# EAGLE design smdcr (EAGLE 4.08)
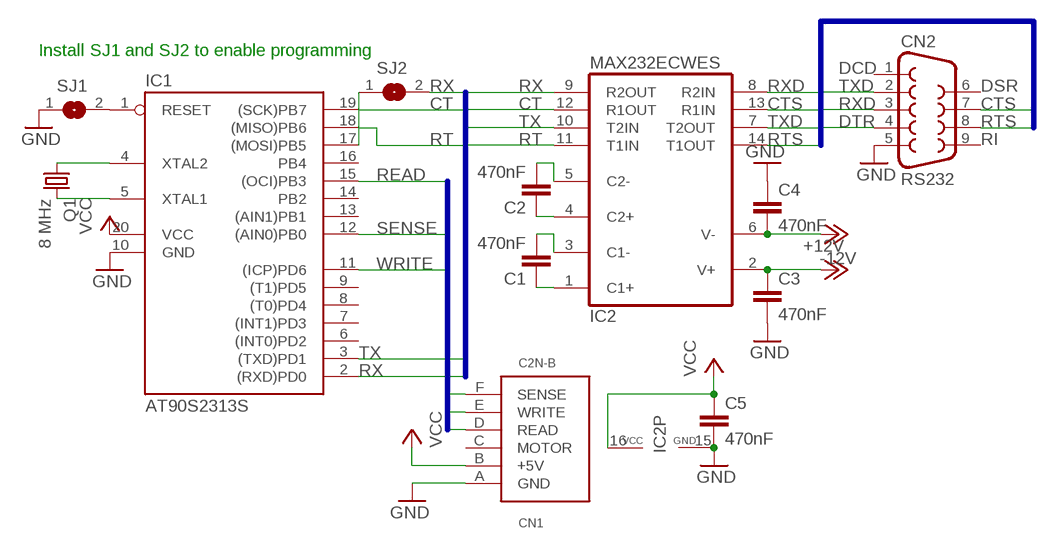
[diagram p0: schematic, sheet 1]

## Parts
C1  470nF  C-EUC0805  [C0805]
C2  470nF  C-EUC0805  [C0805]
C3  470nF  C-EUC0805  [C0805]
C4  470nF  C-EUC0805  [C0805]
C5  470nF  C-EUC0805  [C0805]
CN1  C2N-B  [C2N-B]
CN2  RS232  F09D  [F09D]
IC1  AT90S2313S  [SO-20L]
IC2  MAX232ECWES  [SO16]
Q1  8 MHz  SM49  [SM49]
SJ1  SJ  [SJ]
SJ2  SJW  [SJW]

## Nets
+12V: C3.2 IC2.2(V+)
-12V: C4.1 IC2.6(V-)
C1+: C1.2 IC2.1(C1+)
C1-: C1.1 IC2.3(C1-)
C2+: C2.2 IC2.4(C2+)
C2-: C2.1 IC2.5(C2-)
CT: IC1.19((SCK)PB7) IC2.12(R1OUT)
CTS: CN2.7 IC2.13(R1IN)
DTR: CN2.4
GND: C3.1 C4.2 C5.1 CN1.A(GND) CN2.5 IC1.10(GND) IC2.15(GND) SJ1.1
MOSI: IC1.17((MOSI)PB5) SJ2.1
READ: CN1.D(READ) IC1.15((OCI)PB3)
RESET: IC1.1(RESET) SJ1.2
RT: IC1.18((MISO)PB6) IC2.11(T1IN)
RTS: CN2.8 IC2.14(T1OUT)
RX: IC1.2((RXD)PD0) IC2.9(R2OUT) SJ2.2
RXD: CN2.3 IC2.8(R2IN)
SENSE: CN1.F(SENSE) IC1.12((AIN0)PB0)
TX: IC1.3((TXD)PD1) IC2.10(T2IN)
TXD: CN2.2 IC2.7(T2OUT)
VCC: C5.2 CN1.B(+5V) IC1.20(VCC) IC2.16(VCC)
WRITE: CN1.E(WRITE) IC1.11((ICP)PD6)
XTAL1: IC1.5(XTAL1) Q1.2
XTAL2: IC1.4(XTAL2) Q1.1
Unconnected: CN1.C(MOTOR) CN2.1 CN2.6 CN2.9 IC1.6((INT0)PD2) IC1.7((INT1)PD3) IC1.8((T0)PD4) IC1.9((T1)PD5) IC1.13((AIN1)PB1) IC1.14(PB2) IC1.16(PB4)

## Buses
WRITE,READ,SENSE,MOTOR
DTR,CTS,RTS,RXD,TXD,DSR,RI,DCD
RX,TX,CT,RT

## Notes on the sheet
- Install SJ1 and SJ2 to enable programming
- DCD
- DSR
- RI

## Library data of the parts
C1-C5 = rcl:C-EU: CAPACITOR, European symbol
CN1 = vic-20:C2N: Datassette connector
CN2 = con-subd:F09D: HARTING SUB-D
IC1 = atmel:AT90S2313: MICROCONTROLLER 2 Kbytes FLASH 128 bytes SRAM 128 bytes EEPROM UART
IC2 = maxim:MAX232ECWE: RS232 TRANSCEIVER
Q1 = crystal:SM49: CRYSTAL
SJ1 SJ2 = jumper:SJ: SMD solder JUMPER

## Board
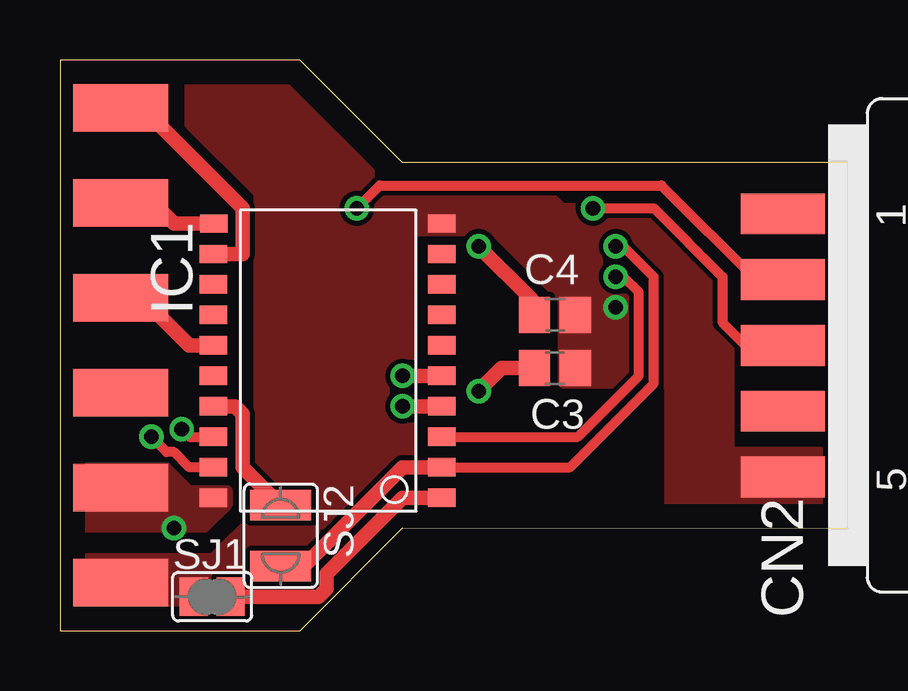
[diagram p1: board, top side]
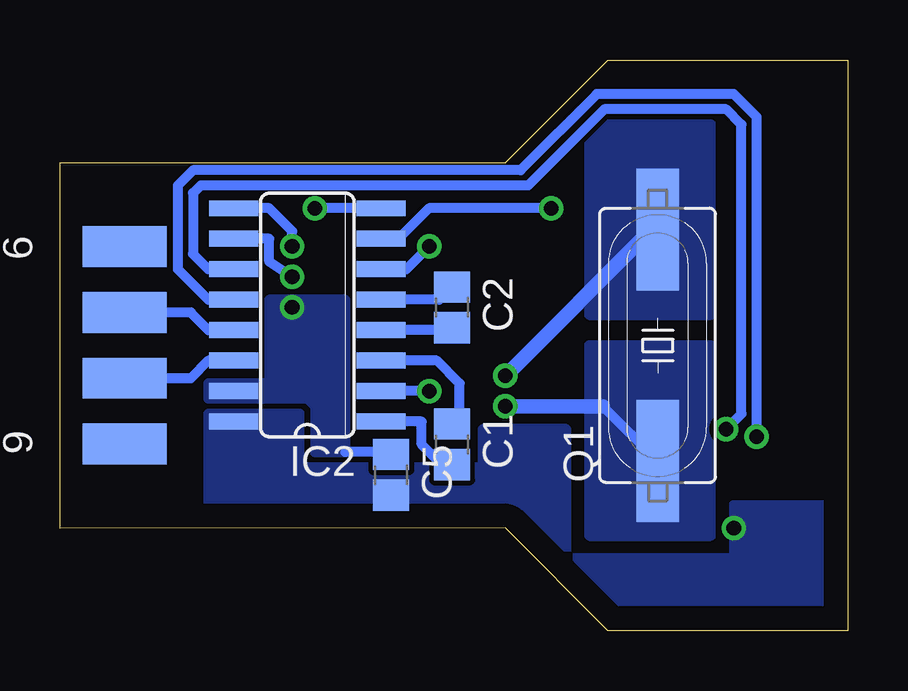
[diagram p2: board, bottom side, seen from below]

Size 32.85 x 23.8 mm. Coordinates in mm from the lower left corner, seen from the top.
Outline: 0,23.8 0,0 10,0 14.28,4.28 32.85,4.28 32.85,19.53 31.75,19.53 31.75,19.52 14.28,19.52 10,23.8 0,23.8
Copper layers used: Top, Bottom

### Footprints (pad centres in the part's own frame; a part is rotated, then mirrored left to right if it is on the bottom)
C0805 = smd 1.3 x 1.5: 1 -0.85,0; 2 0.85,0
C2N-B = smd 1.98 x 3.96 bottom: A -9.9,0; B -5.94,0; C -1.98,0; D 1.98,0; E 5.94,0; F 9.9,0
F09D = smd 1.7 x 3.5: 1 -5.486,-6.045; 2 -2.743,-6.045; 3 0,-6.045; 4 2.743,-6.045; 5 5.486,-6.045 | smd 1.7 x 3.5 bottom: 6 -4.115,-6.045; 7 -1.372,-6.045; 8 1.372,-6.045; 9 4.115,-6.045
SO-20L = smd 0.762 x 1.143: 1 -5.08,-5.131; 2 -3.81,-5.131; 3 -2.54,-5.131; 4 -1.27,-5.131; 5 0,-5.131; 6 1.27,-5.131; 7 2.54,-5.131; 8 3.81,-5.131; 9 5.08,-5.131; 10 6.35,-5.131; 11 6.35,4.369; 12 5.08,4.394; 13 3.81,4.394; 14 2.54,4.394; 15 1.27,4.394; 16 0,4.394; 17 -1.27,4.394; 18 -2.54,4.394; 19 -3.81,4.394; 20 -5.08,4.394
SO16 = smd 0.66 x 2.032: 1 -4.445,-3.073; 2 -3.175,-3.073; 3 -1.905,-3.073; 4 -0.635,-3.073; 5 0.635,-3.073; 6 1.905,-3.073; 7 3.175,-3.073; 8 4.445,-3.073; 9 4.445,3.073; 10 3.175,3.073; 11 1.905,3.073; 12 0.635,3.073; 13 -0.635,3.073; 14 -1.905,3.073; 15 -3.175,3.073; 16 -4.445,3.073
SM49 = smd 5.08 x 1.778: 1 -4.826,0; 2 4.826,0
SJ = smd 1.168 x 1.6: 1 -0.762,0; 2 0.762,0
SJW = smd 1.27 x 2.54: 1 -1.27,0; 2 1.27,0

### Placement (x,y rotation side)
C1  16.51,7.77 270 bottom
C2  16.51,13.49 270 bottom
C3  20.63,10.95 180 top
C4  20.63,13.17 0 top
C5  19.05,6.5 270 bottom
CN1  2.54,11.9 90 bottom
CN2  36.19,11.9 270 top
IC1  10.79,10.63 90 top
IC2  22.54,13.17 90 bottom
Q1  7.93,11.9 90 bottom
SJ1  6.34,1.42 0 top
SJ2  9.2,3.96 270 top

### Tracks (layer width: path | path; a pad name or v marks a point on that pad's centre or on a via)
+12V  (via drill 0.61 pad 0.61)
  Top 0.61: v17.46,10 18.41,10.95 C3.2
  Bottom 0.406: v17.46,10 IC2.2
-12V  (via drill 0.61)
  Top 0.406: C4.1 19.68,13.17
  Top 0.61: v17.46,16.03 19.68,13.81 19.68,13.17
  Bottom 0.406: IC2.6 18.41,15.08 v17.46,16.03
C1+
  Bottom 0.406: C1.2 16.93,6.92 17.78,7.77 17.78,8.73 IC2.1
C1-
  Bottom 0.406: IC2.3 17.14,11.27 16.19,10.31 16.19,8.62 C1.1
C2+
  Bottom 0.406: C2.2 16.4,12.54 IC2.4
C2-
  Bottom 0.406: C2.1 17.04,13.81 IC2.5
CT  (via drill 0.61)
  Top 0.406: v3.81,8.09 4.44,7.46 4.76,7.46 5.39,6.82 IC1.19
  Bottom 0.406: IC2.12 26.67,13.81 27.94,15.08 27.94,18.57 27.3,19.2 13.65,19.2 10.47,22.38 4.76,22.38 3.81,21.43 v3.81,8.09
CTS
  Bottom 0.406: IC2.13 26.67,12.54 27.4,13.27 CN2.7
GND  (via drill 0.61)
  Bottom 0.406: C5.1 19.15,7.46 20.95,7.46
  other vias: 23.17,13.49
  pour Top (no thermals): 20.95,10.31 25.39,10.31 25.39,4.28 31.75,4.28 31.75,7.46 27.94,7.46 27.94,13.81 24.12,17.62 20.95,17.62
  pour Top (no thermals): 20.95,17.62 20,18.57 14.6,18.57 9.84,23.33 5.71,23.33 5.39,23.01 5.39,21.11 8.25,18.25 8.25,4.92 6.34,3.01 -0.01,3.01 -0.01,0.47 14.6,0.47 14.6,16.66 18.09,16.66 20.95,13.81
  pour Bottom (no thermals): 24.12,10.31 26.67,10.31 26.67,9.68 22.54,9.68 22.22,9.36 22.22,7.46 20.95,7.46 20.95,13.81 24.12,13.81
MOSI
  Top 0.61: IC1.17 7.3,9.36 7.62,9.04 7.62,6.82 SJ2.1
READ
  Top 0.61: CN1.D 3.41,13.88 5.39,11.9 IC1.15
RESET
  Top 0.61: IC1.1 14.28,5.55 11.11,2.38 11.11,1.74 10.79,1.42 SJ1.2
RT  (via drill 0.61)
  Top 0.406: v5.08,8.41 5.39,8.09 IC1.18
  Bottom 0.406: IC2.11 26.67,15.08 27.3,15.71 27.3,18.25 26.98,18.57 13.33,18.57 10.15,21.74 5.08,21.74 4.44,21.11 4.44,9.04 v5.08,8.41
RTS
  Bottom 0.406: CN2.8 27.4,10.53 26.67,11.27 IC2.14
RX  (via drill 0.61 pad 0.61)
  Top 0.406: IC1.2 21.27,6.82 24.76,10.31 24.76,14.76 23.49,16.03 v23.17,16.03
  Top 0.61: IC1.2 14.28,6.82 10.15,2.69 SJ2.2
  Bottom 0.406: v23.17,16.03 23.17,16.66 24.12,17.62 IC2.9 26.03,17.62
RXD  (via drill 0.61 pad 0.61)
  Top 0.406: v22.22,17.62 24.76,17.62 27.62,14.76 27.62,12.85 28.57,11.9 CN2.3
  Bottom 0.406: IC2.8 v22.22,17.62
SENSE
  Top 0.406: 3.49,21.74 CN1.F
  Top 0.61: IC1.12 7.62,15.71 7.62,17.62 3.49,21.74
TX  (via drill 0.61 pad 0.61)
  Top 0.406: IC1.3 21.59,8.09 24.12,10.63 24.12,14.12 23.49,14.76 v23.17,14.76
  Bottom 0.406: v23.17,14.76 24.12,15.39 24.12,16.35 IC2.10
TXD  (via drill 0.61 pad 0.61)
  Top 0.406: v12.38,17.62 13.33,18.57 25.08,18.57 29,14.64 CN2.2
  Bottom 0.406: IC2.7 18.73,16.35 17.46,17.62 v12.38,17.62
VCC  (via drill 0.61)
  Bottom 0.406: IC2.16 26.03,8.73
  other vias: 4.76,4.28
  pour Top (no thermals): 6.03,4.28 0.63,4.28 0.63,6.82 4.44,6.82 5.39,5.87 6.98,5.87 6.98,5.23
  pour Bottom (no thermals): 22.86,9.04 26.67,9.04 26.67,0.15 0.31,0.15 0.31,5.23 4.76,5.23 4.76,3.01 11.74,3.01 11.74,8.41 15.23,8.41 15.23,6.82 22.86,6.82
WRITE
  Top 0.61: CN1.E 3.9,17.84 4.76,16.98 IC1.11
XTAL1  (via drill 0.61)
  Top 0.61: v14.28,10.63 IC1.5
  Bottom 0.406: Q1.2 8.19,16.73
  Bottom 0.61: 8.19,16.73 v14.28,10.63
  pour Bottom (no thermals): 5.71,21.11 10.79,21.11 10.79,13.17 5.71,13.17
XTAL2  (via drill 0.61)
  Top 0.61: v14.28,9.36 IC1.4
  Bottom 0.406: Q1.1 10.22,9.36
  Bottom 0.61: 10.22,9.36 v14.28,9.36
  pour Bottom (no thermals): 5.71,11.9 10.79,11.9 10.79,3.96 5.71,3.96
